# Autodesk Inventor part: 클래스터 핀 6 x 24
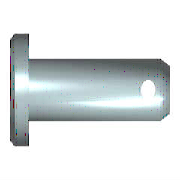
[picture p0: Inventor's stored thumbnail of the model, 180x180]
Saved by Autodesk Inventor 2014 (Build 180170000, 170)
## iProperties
IsCustomPart: 1
Created: 2012-02
Part Number: 클래스터 핀 6 x 24
Material: 강철
Description: 머리가 있는 클레비스 핀
Document SubType Name: Modeling
Standard: ISO 2341
Designer: mduedu
Standard Revision: Second edition 1986-11-01
Standards Organization: ISO
Language: ko-KR
Size Designation: B - 6 x 24
Categories: <MemberInstance><Categories><Category DisplayName="조임쇠" InternalName="e4da775c-781d-43d5-af7c-5136215cf5a6" Mnemonic="FSTN"><Category DisplayName="핀" InternalNa
Density: 7.85 g/cm^3
Appearance: Orange
Author: mduedu
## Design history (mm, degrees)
sketch "스케치1"
  geometry: L1 (-2, 0)-(-2, 5); L2 (-2, 5)-(0, 5); L3 (0, 5)-(0, 3); L4 (0, 3)-(24, 3); L5 (24, 3)-(24, 0); L6 (-2, 0)-(24, 0); L7 (-4, 0)-(17, 0) reference; L8 (0, -0.98)-(0, 3.08) reference; C1 r 0.8 at (20.8, 0)
  constraints: 12 end point, 3 parallel, 2 collinear, 2 perpendicular, 1 centre point, 1 point on line, 1 vertical
  dimensions: "d0" = 6 diameter of L4 L6 (= NND); "d1" = 10 diameter of L2 L6 (= KOD); "d2" = 2 distance of L1.end L2.end (= KOH); "d3" = 24 distance of L3.end L4.end (= NLG); "d5" = 3.2 distance from line of L5 C1.centre (= DIST); "d6" = 1.6 diameter of C1 (= BOR)
revolve "본체" stored, may be unused: angle "d4" = 90 deg
extrude "구멍" cut sketch "스케치1" stored distance "d7" = 6 (= NND); taper "d8" = 0 deg
body "Solid1"
chamfer "모따기1" distance "d9" = 1 (= PHH2); stored, may be unused: angle "d10" = 45 deg (= FAWI2), second distance "d16" = 1 (= PHH2)
chamfer "모따기2" distance "d11" = 2 (= PHH1); stored, may be unused: angle "d12" = 30 deg (= FAWI1), second distance "d17" = 2 (= PHH1)
workaxis "Work Axis1"
workplane "Work Plane1"
other parameters: "PHH1" = 2 [user parameter; used in 2 equation terms], "PHH2" = 1 [user parameter; used in 2 equation terms], "KOD" = 10 [user parameter; used in 1 equation term], "KOH" = 2 [user parameter; used in 1 equation term], "NND" = 6 [user parameter; used in 2 equation terms], "FAWI1" = 30 deg [user parameter; used in 1 equation term], "FAWI2" = 45 deg [user parameter; used in 1 equation term], "DIST" = 3.2 [user parameter; used in 1 equation term], "BOR" = 1.6 [user parameter; used in 1 equation term], "NLG" = 24 [user parameter; used in 1 equation term], "d13" = 0, "d14" = 0, "d27" = 0, "d28" = 0, "d29" = 0, "d30" = 0, "d31" = 0
